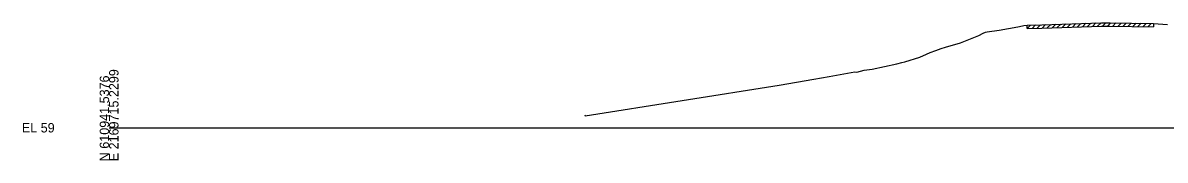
# Model space of a CAD drawing. Extents: x -26 to 6803, y -10 to 19606.
# Drawn here: x 1974.3 to 2314.5, y 6990.3 to 7031.3 of the extents above; entities that cross this region are included whole.
import ezdxf

# ---------------------------------------------------------------- set-up
doc = ezdxf.new("R2010")
doc.units = 0
for name, color, linetype in [('RD_GPK_XS_Cell', 7, 'Continuous'), ('RD_XS_ExGround', 7, 'Continuous'), ('RD_XS_ExPaveRet', 7, 'Continuous')]:
    doc.layers.add(name, color=color, linetype=linetype)

msp = doc.modelspace()

# ---------------------------------------------------------------- linework, layer by layer
at = {"layer": 'RD_GPK_XS_Cell'}
msp.add_line((2000, 7000), (2400, 7000), dxfattribs=at)
at = {"layer": 'RD_XS_ExGround'}
msp.add_lwpolyline([(2141.65, 7003.81), (2141.81, 7003.58), (2199.58, 7012.75), (2209.86, 7014.47), (2214.42, 7015.32), (2222.13, 7016.71), (2222.73, 7016.62), (2224.9, 7017.16), (2227.29, 7017.49), (2234.61, 7019.12), (2236.06, 7019.45), (2237.04, 7019.7), (2241.51, 7021.1), (2243.48, 7022.01), (2244.59, 7022.5), (2246.25, 7023.1), (2247.81, 7023.64), (2249.12, 7024.04), (2253.57, 7025.32), (2259, 7027.59), (2260.35, 7028.22), (2261.06, 7028.51), (2261.51, 7028.62), (2265.11, 7029.19), (2270.66, 7030.18), (2272.01, 7030.48), (2272.42, 7030.51), (2273.4, 7030.64), (2277.79, 7030.78), (2295.56, 7031.35), (2298.03, 7031.31), (2311.07, 7031.14), (2315.26, 7030.84)], dxfattribs=at)
at = {"layer": 'RD_XS_ExPaveRet'}
for p, q in [((2273.4, 7029.64), (2274.43, 7030.67)), ((2273.4, 7029.64), (2273.4, 7030.64)), ((2273.4, 7029.64), (2277.79, 7029.78)), ((2274.9, 7029.68), (2275.93, 7030.72)), ((2276.4, 7029.73), (2277.43, 7030.77)), ((2277.79, 7029.78), (2295.56, 7030.35)), ((2277.9, 7029.78), (2278.93, 7030.81)), ((2279.4, 7029.83), (2280.43, 7030.86)), ((2280.9, 7029.88), (2281.93, 7030.91)), ((2282.4, 7029.92), (2283.43, 7030.96)), ((2283.9, 7029.97), (2284.93, 7031.01)), ((2285.4, 7030.02), (2286.43, 7031.05)), ((2286.9, 7030.07), (2287.93, 7031.1)), ((2288.4, 7030.12), (2289.43, 7031.15)), ((2289.9, 7030.16), (2290.93, 7031.2)), ((2291.4, 7030.21), (2292.43, 7031.25)), ((2292.9, 7030.26), (2293.93, 7031.29)), ((2294.4, 7030.31), (2295.43, 7031.34)), ((2295.56, 7030.35), (2298.03, 7030.31)), ((2295.9, 7030.34), (2296.88, 7031.33)), ((2297.4, 7030.32), (2298.38, 7031.31)), ((2298.03, 7030.31), (2311.07, 7030.14)), ((2298.9, 7030.3), (2299.88, 7031.29)), ((2300.4, 7030.28), (2301.38, 7031.27)), ((2301.9, 7030.26), (2302.88, 7031.25)), ((2303.4, 7030.24), (2304.38, 7031.23)), ((2304.9, 7030.22), (2305.88, 7031.21)), ((2306.4, 7030.2), (2307.38, 7031.19)), ((2307.9, 7030.18), (2308.88, 7031.17)), ((2309.4, 7030.16), (2310.38, 7031.15)), ((2311.07, 7031.14), (2311.07, 7030.14)), ((2311.07, 7030.14), (2311.07, 7030.14))]:
    msp.add_line(p, q, dxfattribs=at)

# ---------------------------------------------------------------- texts
at = {"layer": 'RD_GPK_XS_Cell'}
for s, p in [('N 610941.5376', (2000, 6990)), ('E 2169715.2299', (2002.8, 6990))]:
    msp.add_text(s, height=2.8, rotation=90, dxfattribs=at).set_placement(p)
msp.add_text('EL 59', height=2.8, dxfattribs=at).set_placement((1974, 6998.6))

doc.saveas('drawing.dxf')
